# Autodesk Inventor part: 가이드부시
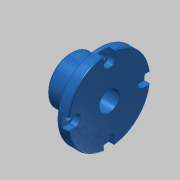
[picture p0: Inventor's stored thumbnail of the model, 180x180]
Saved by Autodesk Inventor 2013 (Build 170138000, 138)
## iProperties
Created: 2019-05
Part Number: 가이드부시
Material: 알루미늄 6061
Document SubType Name: Modeling
Designer: mduedu
Density: 1 g/cm^3
Author: mduedu
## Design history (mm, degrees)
sketch "스케치1"
  geometry: C1 r 29 at (0, 0); 1 further point
  constraints: 1 centre point, 1 coincident
  dimensions: "d0" = 58 diameter of C1
extrude "돌출1" new body sketch "스케치1" distance "d1" = 7; taper "d2" = 0 deg
sketch "스케치2" dims "d3" = 48
  geometry: L1 (-4, 24)-(-4, 28.723); L2 (4, 24)-(4, 28.723); A1 r 4 centre (0, 24) between (-4, 24) and (4, 24); A2 r 29 centre (0, 0) between (-4, 28.723) and (4, 28.723) reference; A3 r 29 centre (0, 0) between (4, 28.723) and (-4, 28.723); 2 further points
  constraints: 6 point on circle, 4 end point, 2 centre point, 2 coincident, 2 tangent, 2 vertical alignment, 1 parallel, 1 vertical, 2 other
  dimensions: "d4" = 8 distance between parallel lines of L2 L1
extrude "돌출2" cut sketch "스케치2" distance "d5" = 4.4; taper "d6" = 0 deg
fillet "모깎기1" dims "d10" = 1
sketch "스케치3"
  geometry: C1 r 16.5 at (0, 0); 1 further point
  constraints: 1 centre point, 1 coincident
  dimensions: "d11" = 33 diameter of C1
extrude "돌출3" join sketch "스케치3" distance "d12" = 20; taper "d13" = 0 deg
sketch "스케치4"
  geometry: C1 r 7 at (0, 0); 1 further point
  constraints: 1 centre point, 1 coincident
  dimensions: "d14" = 14 diameter of C1
extrude "돌출4" cut sketch "스케치4" stored distance "d15" = 20; taper "d16" = 0 deg
chamfer "모따기1" distance "d17" = 1; stored, may be unused: second distance "d18" = 2, angle "d19" = 45 deg
chamfer "모따기2" distance "d20" = 1; stored, may be unused: second distance "d21" = 2, angle "d22" = 45 deg
sketch "스케치5" dims "d23" = 48
  geometry: 6 further points
  constraints: 2 vertical alignment, 1 coincident, 7 other
  dimensions: "d26" = 360 deg dimension on point (24, 0) point (24, 24) (derived)
sketch "스케치6"
  geometry: 4 further points
  constraints: 4 other
hole "구멍1" sketch "스케치6" at (-24, 24), (-48, 0), (-24, -24), (0, 0) diameter "d28" = 4.5; stored, may be unused: countersink angle "d32" = 90 deg, drill point angle "d34" = 0 deg; dims "d29" = 6, "d30" = 4, "d31" = 2, "d33" = 8
node "솔리드1"
pattern_circular "원형 패턴1" dims angle "d8" = 360 deg
